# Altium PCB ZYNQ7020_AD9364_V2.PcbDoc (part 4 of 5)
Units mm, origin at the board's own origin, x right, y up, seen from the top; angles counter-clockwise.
Board outline 88.95 x 91.52 mm, 4 copper layers (Top Layer, Layer 1, Layer 2, Bottom Layer), stack 0.603 mm thick; 285 components, 278 nets, 1497 pads, 1247 vias.
Unrouted connection lines stored in the file: 367.
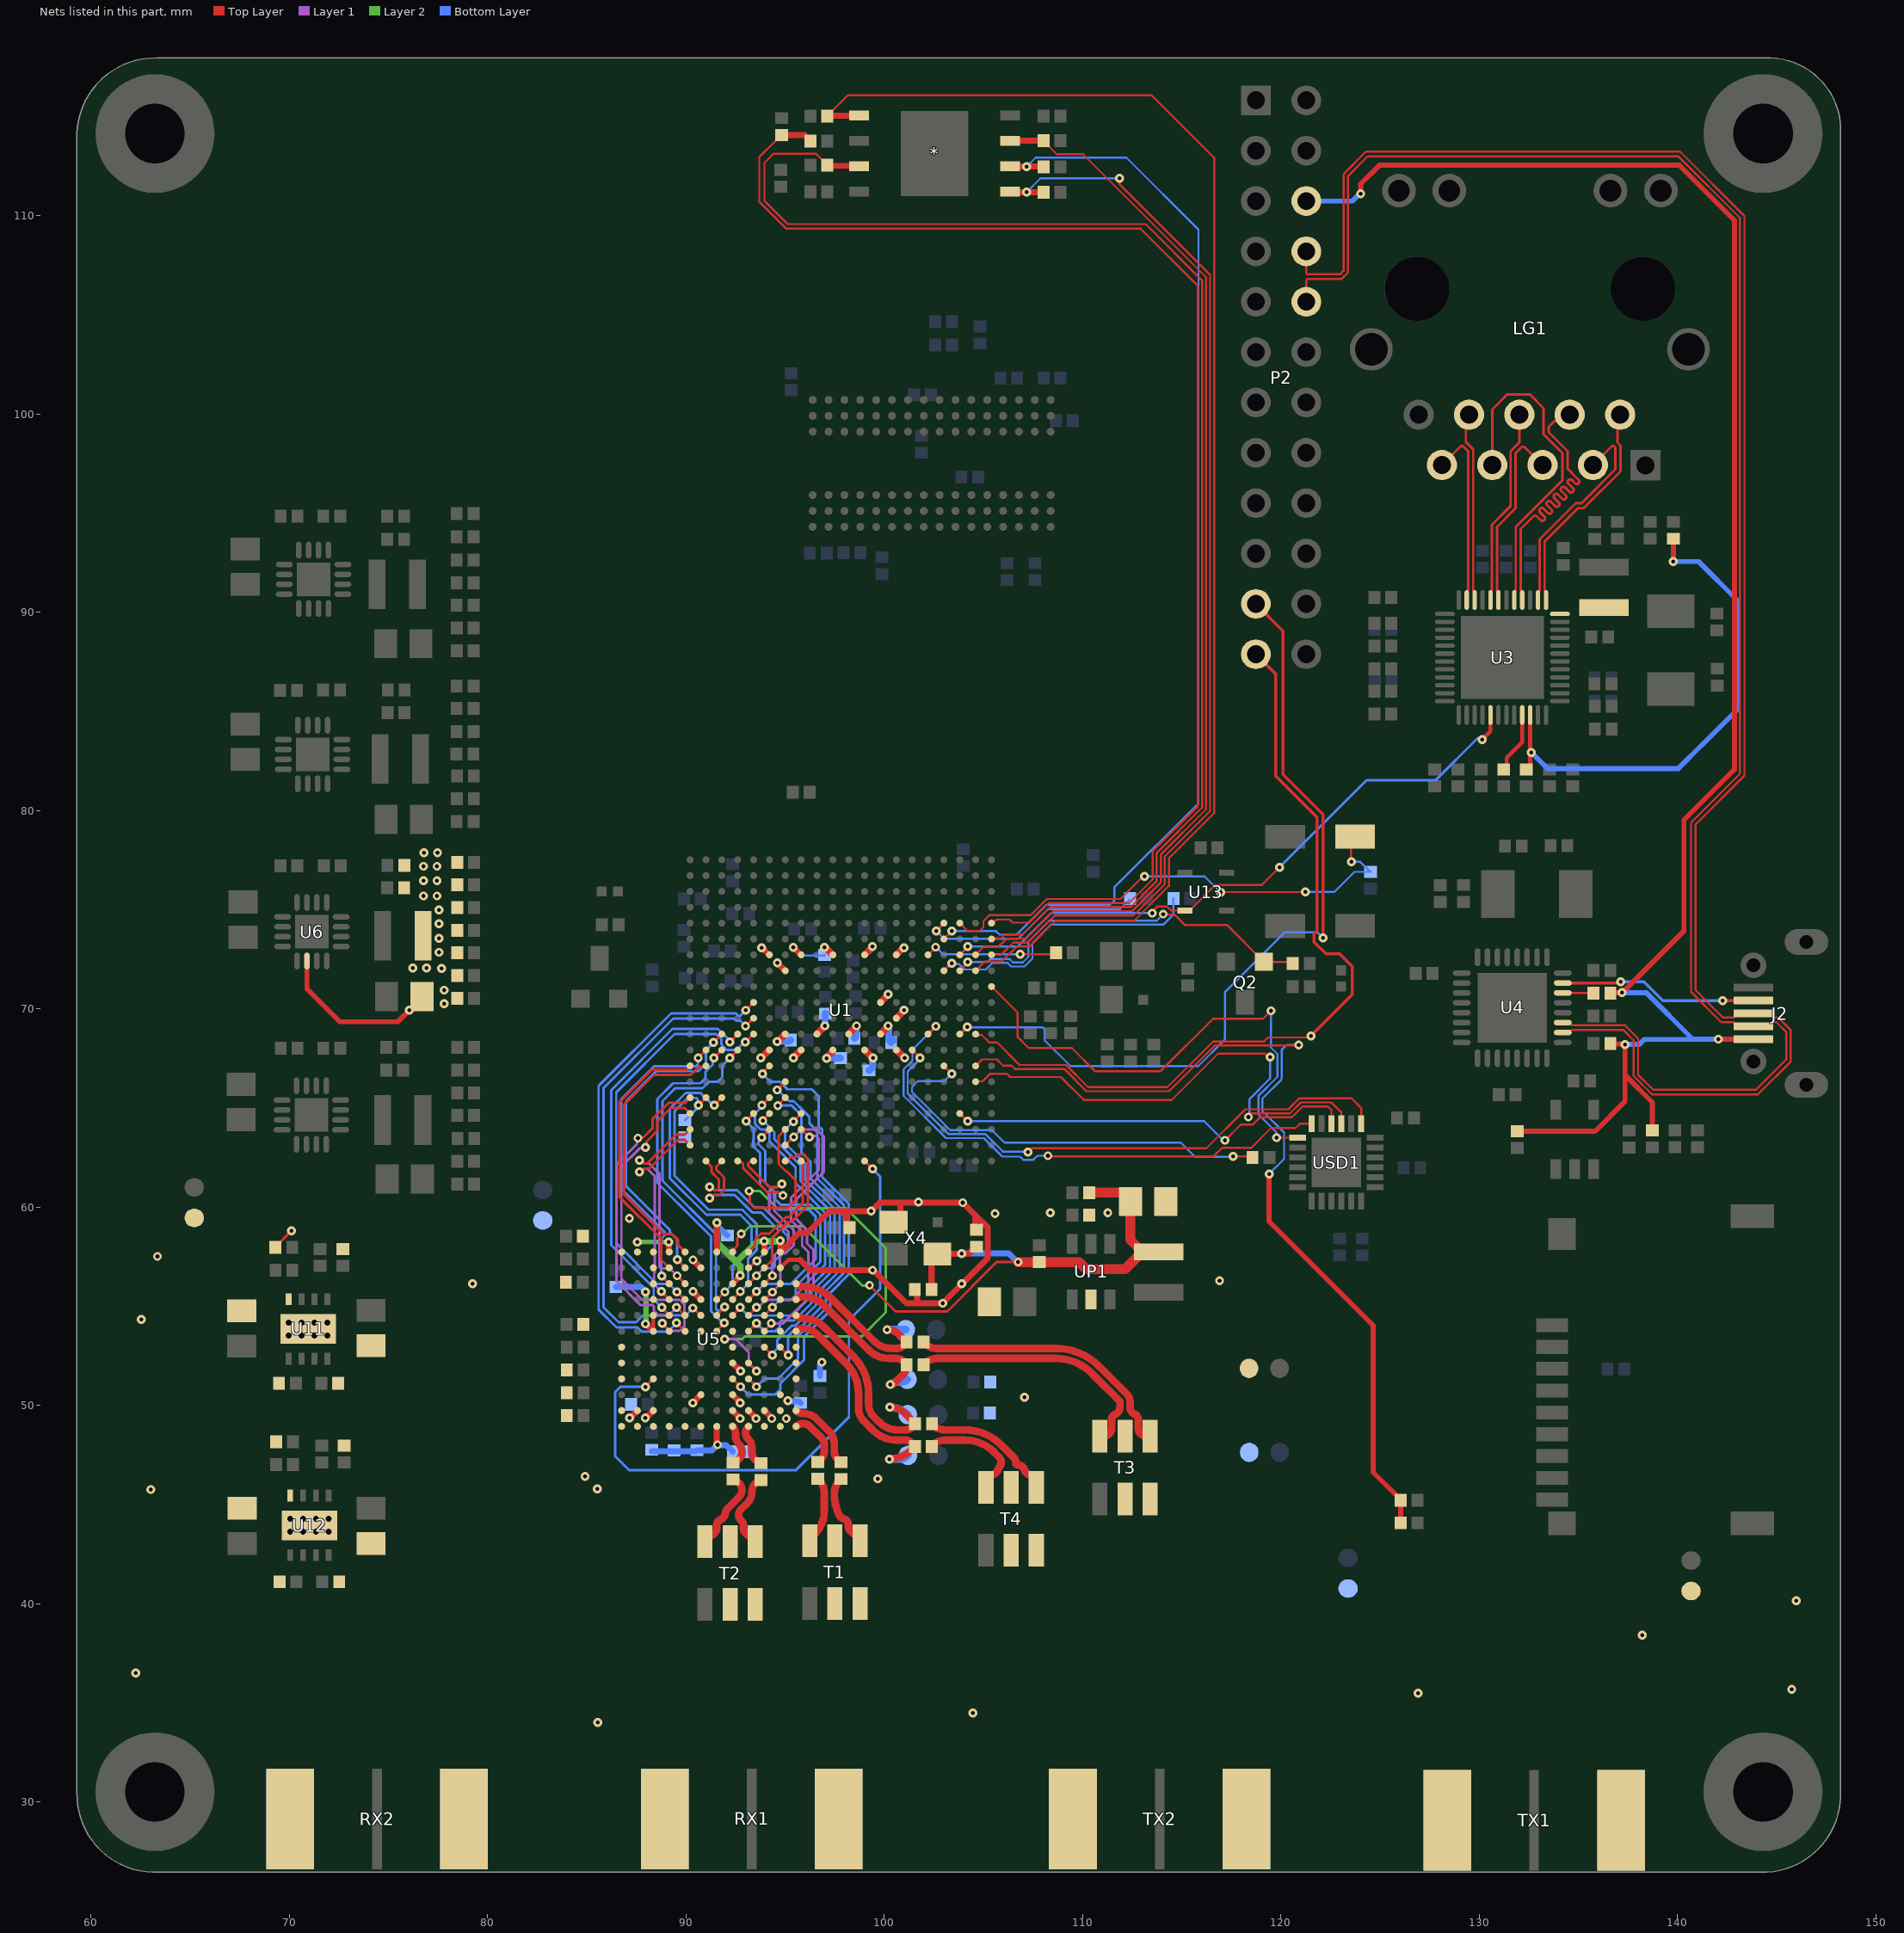
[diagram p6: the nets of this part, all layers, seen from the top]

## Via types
v1: diameter 0.45, hole 0.2, Top Layer to Bottom Layer, tented both sides, 995 vias
v2: diameter 0.406, hole 0.254, Top Layer to Bottom Layer, tented both sides, 118 vias
v3: diameter 1, hole 0.5, Top Layer to Bottom Layer, 116 vias
v4: diameter 0.5, hole 0.3, Top Layer to Bottom Layer, tented both sides, 16 vias
v5: diameter 0.406, hole 0.254, Top Layer to Bottom Layer, 2 vias

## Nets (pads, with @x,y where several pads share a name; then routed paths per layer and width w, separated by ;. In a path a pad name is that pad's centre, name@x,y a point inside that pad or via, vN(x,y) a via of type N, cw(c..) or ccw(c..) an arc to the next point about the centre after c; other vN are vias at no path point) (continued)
PHY_AD1/LED1: R32.1 R40.2 U3.34 | length 25.5
  Top Layer w0.203: R40.2@132.386,82.068 132.576,82.258 U3.34@132.576,84.818
  Top Layer w0.254: v1@139.802,92.583 R32.1@139.802,93.707
  Bottom Layer w0.254: v1(132.632,82.934) 133.447,82.118 140.05,82.118 141.26,83.327 141.265,83.327 143.053,85.115 143.053,90.576 141.069,92.561 v1(139.794,92.561)
PHY_MDI0_N: LG1.P3 U3.2 | length 11
  Top Layer w0.127: U3.2@132.976,90.618 132.976,91.033 133.049,91.106 133.049,93.674 134.877,95.503 135.168,95.503 136.878,97.213 136.878,98.306 136.804,98.381 136.699,98.381 LG1.P3@135.743,97.425
PHY_MDI0_P: LG1.P2 U3.1 | length 11.2
  Top Layer w0.127: U3.1@133.376,90.618 133.376,91.033 133.303,91.106 133.303,93.569 134.982,95.249 135.273,95.249 137.132,97.108 137.132,98.412 136.984,98.56 136.984,99.837 LG1.P2@137.112,99.965
PHY_MDI1_N: LG1.P7 U3.5 | length 17.1
  Top Layer w0.127: LG1.P7@130.663,97.425 130.663,100.233 131.42,100.99 132.563,100.99 133.254,100.299 133.254,98.975 133.328,98.901 134.212,98.017 134.212,96.671 131.849,94.308 131.849,91.106 131.776,91.033 U3.5@131.776,90.618
PHY_MDI1_P: LG1.P4 U3.4 | length 17.1
  Top Layer w0.127: U3.4@132.176,90.618 132.176,91.033 132.103,91.106 132.103,94.202 132.552,94.651 132.776,94.876 132.884,94.876 133.146,94.613 133.254,94.613 133.326,94.685 133.326,94.793 133.046,95.073 133.046,95.181 133.117,95.253 133.225,95.253 133.506,94.973 133.613,94.973 133.685,95.044 133.685,95.152 133.405,95.433 133.405,95.54 133.477,95.612 133.584,95.612 133.865,95.332 133.973,95.332 134.044,95.404 134.044,95.511 133.764,95.792 133.764,95.9 133.836,95.971 133.944,95.971 134.224,95.691 134.332,95.691 134.404,95.763 134.404,95.871 134.123,96.151 134.123,96.259 134.195,96.331 134.303,96.331 134.583,96.05 134.691,96.05 134.763,96.122 134.763,96.23 134.473,96.52 134.473,96.628 134.545,96.7 134.652,96.7 134.876,96.475 134.984,96.475 135.056,96.547 135.056,96.655 134.466,97.245 134.466,97.361 134.466,98.122 133.508,99.08 133.508,99.349 133.801,99.642 133.871,99.642 134.194,99.965 LG1.P4@134.572,99.965
PHY_MDI2_N: LG1.P6 U3.8 | length 9.9
  Top Layer w0.127: U3.8@130.576,90.618 130.576,91.033 130.649,91.106 130.649,94.415 131.59,95.356 131.59,98.13 132.032,98.572 LG1.P6@132.032,99.965
PHY_MDI2_P: LG1.P5 U3.7 | length 9.7
  Top Layer w0.127: U3.7@130.976,90.618 130.976,91.033 130.903,91.106 130.903,94.31 131.844,95.251 131.844,98.025 132.17,98.352 132.276,98.352 LG1.P5@133.203,97.425
PHY_MDI3_N: LG1.P9 U3.11 | length 9.4
  Top Layer w0.127: LG1.P9@128.123,97.425 129.079,98.381 129.184,98.381 129.449,98.116 129.449,91.106 129.376,91.033 U3.11@129.376,90.618
PHY_MDI3_P: LG1.P8 U3.10 | length 9.6
  Top Layer w0.127: LG1.P8@129.492,99.965 129.332,99.805 129.332,98.592 129.703,98.221 129.703,91.106 129.776,91.033 U3.10@129.776,90.618
PMEB: R35.2 U3.33 | length 3.1
  Top Layer w0.203: R35.2@131.243,82.068 131.395,82.221 131.395,82.659 132.176,83.44 U3.33@132.176,84.818
PS_CLK_500: R37.1 U1.E7 | length 6.8
  Top Layer w0.102: U1.E7@102.21,72.72 102.21,72.723 v1(102.595,73.11) v1(102.595,73.11) ; v1(106.858,72.746) 108.585,72.746 R37.1@108.661,72.822
  Bottom Layer w0.102: v1(102.595,73.11) 102.611,73.11 102.976,72.746 v1(106.858,72.746)
PS_MIO7: R56.2 U1.D8 | length 14.4
  Top Layer w0.127: U1.D8@103.01,71.92 v1@103.403,72.314
  Bottom Layer w0.102: v1(103.403,72.288) 103.442,72.25 103.781,72.25 104.047,71.984 105.123,71.984 105.454,72.315 106.222,72.315 106.401,72.136 107.069,72.136 107.471,72.538 107.471,73.318 108.398,74.244 114.072,74.244 114.586,74.759 R56.2@114.586,75.565
PS_MIO8: R47.2 U1.D5 | length 11.2
  Top Layer w0.127: v1(102.633,73.923) 102.633,73.933 103.01,74.31 U1.D5@103.01,74.32
  Bottom Layer w0.102: v1(102.633,73.923) 103.023,73.533 106.756,73.533 108.255,75.032 111.893,75.032 R47.2@112.349,75.487
PS_PRO_B: U1.C7 U3.29 U13.2 | length 32.6
  Top Layer w0.102: U1.C7@103.81,72.72 104.203,73.114 v1(104.203,73.136) ; v1(113.516,74.825) 113.516,74.908 113.763,75.155 114.28,75.155 114.479,74.955 U13.2@115.174,74.955 115.402,74.955 116.698,76.251 119.05,76.251 v1(119.939,77.14)
  Top Layer w0.203: v1(130.153,83.576) 130.576,83.999 U3.29@130.576,84.818
  Bottom Layer w0.102: v1(104.203,73.136) 106.715,73.136 108.407,74.828 113.512,74.828 v1(113.516,74.825)
  Bottom Layer w0.127: v1(119.939,77.14) 124.333,81.534 127.813,81.534 129.936,83.657 130.079,83.657 130.079,83.651 v1(130.153,83.576)
QSPI_CS: *.1 R59.1 U1.A7 | length 55.3
  Top Layer w0.102: U1.A7@105.41,72.72 105.893,72.72 106.513,73.341 107.242,73.341 108.602,74.701 112.571,74.701 114.148,76.278 114.148,77.648 ; v1(111.862,111.887) 111.862,111.598 116.434,107.026 116.434,79.979 114.148,77.693
  Top Layer w0.3: *.1@106.34,111.212 106.358,111.194 v1(107.186,111.194) 108.015,111.194 R59.1@108.033,111.176
  Bottom Layer w0.102: v1(107.186,111.194) 107.88,111.887 v1(111.862,111.887)
QSPI_D0: *.5 R49.2 U1.B8 | length 72.1
  Top Layer w0.102: R49.2@97.123,115.037 97.123,115.062 97.372,115.311 97.397,115.311 98.164,116.078 113.487,116.078 116.637,112.928 116.637,79.869 114.358,77.59 114.358,76.201 112.605,74.447 108.636,74.447 107.326,73.138 106.669,73.138 105.91,72.379 105.068,72.379 U1.B8@104.61,71.92
  Top Layer w0.3: R49.2@97.123,115.037 97.13,115.044 98.732,115.044 *.5@98.74,115.052
QSPI_D1: *.2 R51.2 U1.D6 | length 57.2
  Top Layer w0.102: U1.D6@103.01,73.52 103.403,73.914 v1(103.403,73.918)
  Top Layer w0.3: *.2@106.34,112.492 106.35,112.481 v1(107.186,112.481) 108.023,112.481 R51.2@108.033,112.471
  Bottom Layer w0.102: v1(103.403,73.918) 105.635,73.918 105.813,73.74 106.676,73.74 108.171,75.235 111.371,75.235 111.603,75.467 111.603,76.119 115.849,80.365 115.849,109.296 112.217,112.928 107.633,112.928 v1(107.186,112.481)
QSPI_D2: *.3 R52.2 U1.B7 | length 55.1
  Top Layer w0.102: U1.B7@104.61,72.72 105.016,73.127 105.766,73.127 106.183,73.544 107.158,73.544 108.544,74.93 112.513,74.93 113.944,76.362 113.944,77.777 116.23,80.063 116.23,106.898 110.023,113.106 108.701,113.106 108.04,113.767 R52.2@108.04,113.792
  Top Layer w0.3: *.3@106.34,113.772 106.35,113.782 108.03,113.782 R52.2@108.04,113.792
QSPI_D3: *.7 R50.2 U1.A6 | length 71.7
  Top Layer w0.102: R50.2@97.123,112.547 97.123,112.572 96.564,113.132 94.412,113.132 93.955,112.674 93.955,110.748 95.125,109.578 113.188,109.578 116.027,106.739 116.027,80.148 113.741,77.862 113.741,76.446 112.428,75.133 108.371,75.133 106.985,73.747 106.099,73.747 105.901,73.55 105.439,73.55 U1.A6@105.41,73.52
  Top Layer w0.3: R50.2@97.123,112.547 97.151,112.519 98.712,112.519 *.7@98.74,112.492
QSPI_SCK: R53.2 R58.2 U1.A5 | length 69.4
  Top Layer w0.102: R53.2@94.818,114.078 94.793,114.078 94.544,113.829 94.544,113.804 93.701,112.961 93.701,110.715 95.068,109.347 112.928,109.347 115.824,106.451 115.824,80.232 113.538,77.946 113.538,76.53 112.344,75.336 108.287,75.336 107.296,74.346 106.473,74.346 106.324,74.495 105.651,74.495 105.477,74.32 U1.A5@105.41,74.32
  Top Layer w0.3: R53.2@94.818,114.078 95.986,114.078 96.273,113.792 R58.2@96.273,113.767
REG_OUT: L6.1 U3.48 | length 0.8
  Top Layer w0.203: L6.1@135.528,90.246 L6.1@136.296,90.246
RFGND: C17.1 C18.1 C20.1 C21.1 C22.1 C23.1 C25.1 C26.1 C27.1 C28.1 C58.2 C59.1 C60.2 C63.1 C142.2 C143.1 C144.1 C145.1 C146.1 C150.1 C151.1 C166.2 C170.2 C172.2 C174.2 C175.2 C177.2 CP1.1 CP3.1 R24.2 R25.2 R75.2 RP1.2 RX1.2 RX1.3 RX1.4 RX1.5 RX2.2 RX2.3 RX2.4 RX2.5 RX5.1 RX6.1 RX7.1 RX8.1 RX10.1 RX13.1 RX14.1 RX15.1 RX22.1 T1.1 T1.2 T1.5 T2.1 T2.2 T2.5 T3.1 T3.2 T3.5 T4.1 T4.2 T4.5 TX1.2 TX1.3 TX1.4 TX1.5 TX2.2 TX2.3 TX2.4 TX2.5 U5.A1 U5.A2 U5.A4 U5.A5 U5.A6 U5.A12 U5.B1 U5.B2 U5.B12 U5.C1 U5.C2 U5.C7 U5.C8 U5.C9 U5.C10 U5.C11 U5.C12 U5.D1 U5.D12 U5.E1 U5.F1 U5.F3 U5.F7 U5.F9 U5.F11 U5.G1 U5.G12 U5.H2 U5.H3 U5.H5 U5.H6 U5.H7 U5.H10 U5.J2 U5.K1 U5.K2 U5.K12 U5.L1 U5.L2 U5.L3 U5.L7 U5.L8 U5.L9 U5.L10 U5.L11 U5.L12 U5.M4 U5.M5 U5.M6 U11.0 U11.4 U12.0 U12.4 UP1.2 X4.2 | length 59.5
  Top Layer w0.127: R24.2@69.296,57.967 69.296,57.992 v1@70.105,58.801
  Top Layer w0.2: U5.C7@88.354,53.734 88.354,53.747 U5.C8@88.354,54.534
  Top Layer w0.203: U5.L11@94.754,56.934 95.154,57.334 95.765,57.334
  Top Layer w0.3: U5.G1@91.554,48.934 91.554,48.044 v1(91.592,48.006) ; U5.H10@92.354,56.134 v1@92.705,56.485
  Top Layer w0.305: v1@87.181,49.361 U5.B2@87.554,49.734 ; v1(87.951,54.104) 87.971,54.104 88.331,53.744 88.351,53.744 U5.C7@88.354,53.747 ; v1@87.981,49.361 U5.C2@88.354,49.734 ; v1(89.138,58.24) 89.146,58.232 89.146,57.742 U5.D12@89.148,57.741 ; v1(90.354,55.734) U5.F9@90.754,55.334 ; v1(90.357,57.334) v1(90.357,57.334) 90.754,56.935 U5.F11@90.754,56.934 ; v1@90.381,50.161 U5.F3@90.754,50.534 ; U5.G12@91.554,57.734 91.567,57.747 v1(91.567,59.207) ; U5.H2@92.354,49.734 v1@92.727,49.361 ; U5.H3@92.354,50.534 v1@92.727,50.161 ; U5.H5@92.354,52.134 v1(92.754,51.734) ; U5.J2@93.154,49.734 v1@93.527,49.361 ; v1(93.949,58.273) 93.952,58.27 93.952,57.737 U5.K12@93.954,57.734 ; U5.K2@93.954,49.734 v1@94.328,49.361 ; U5.L12@94.754,57.734 95.694,58.674 96.114,58.674 97.231,59.792 97.866,59.792 ; U5.L12@94.756,57.758 94.756,58.3 v1(94.758,58.302) ; v1@95.034,49.357 v1(95.062,49.329) ; 95.765,57.334 96.285,56.814 v1(99.406,56.814) 99.447,56.814 101.117,55.143 101.752,55.143 ; C150.1@98.247,58.953 98.1,59.101 98.1,59.558 97.866,59.792 ; X4.2@100.482,59.233 100.813,59.563 100.813,60.223 ; C143.1@101.537,55.829 101.651,55.716 101.651,55.245 101.752,55.143 ; C144.1@104.648,58.852 104.595,58.905 104.595,59.591 ; 97.866,59.792 v1(99.339,59.792) 99.771,60.223 100.813,60.223 ; 100.813,60.223 v1(103.962,60.223) 104.595,59.591 ; 101.752,55.143 v1(102.946,55.143) 105.227,57.424 105.227,58.041 105.227,58.958 104.595,59.591
  Layer 2 w0.127: v1@89.129,58.232 v1(89.138,58.24) ; 92.519,57.239 92.547,57.239
  Layer 2 w0.25: v1(87.546,58.232) v1@89.129,58.232
  Layer 2 w0.3: v1@87.981,54.104 v1@87.981,55.753 ; 92.547,57.239 93.581,58.273 v1(93.949,58.273)
  Layer 2 w0.35: v1(91.567,59.207) 91.567,58.191 92.519,57.239 92.735,57.023 v1(92.735,56.54) ; v1(93.949,58.273) v1@94.758,58.273
  Bottom Layer w0.3: C170.2@86.462,55.963 87.73,55.963 87.94,55.753 v1@87.981,55.753 ; C172.2@88.265,47.679 90.497,47.679 C174.2@90.551,47.733 91.32,47.733 v1(91.592,48.006) 91.621,47.977 92.034,47.977 92.186,47.825 92.211,47.825 92.361,47.675 RX5.1@92.361,47.65 ; C166.2@96.749,51.479 96.749,52.07 v1(96.85,52.172)
  Bottom Layer w0.305: v1(91.567,59.207) 91.595,59.18 91.595,59.046 92.075,58.566 RX22.1@92.1,58.566 ; v1(95.148,50.236) 95.175,50.208 95.696,50.208 R75.2@95.783,50.121
  other v1: 85.554,33.999 104.477,34.482 126.93,35.472 145.767,35.665 62.252,36.504 138.223,38.409 145.99,40.148 63.014,45.749 85.528,45.785 99.676,46.293 84.912,46.406 92.727,49.329 93.527,49.329 94.328,49.329 87.149,49.361 87.949,49.361 90.348,50.114 92.727,50.129 107.068,50.407 62.531,54.334 87.96,55.728 79.244,56.138 103.911,56.134 116.913,56.29 63.344,57.509 70.105,58.808 87.147,59.436 105.588,59.665 108.382,59.715 111.274,59.719 101.727,60.249
  other v4: 70.038,43.618 70.688,43.618 71.338,43.618 71.988,43.618 70.038,44.268 70.688,44.268 71.338,44.268 71.988,44.268 69.967,53.523 70.617,53.523 71.267,53.523 71.917,53.523 69.967,54.173 70.617,54.173 71.267,54.173 71.917,54.173
RX1A_N: C16.2 U5.M2 | length 3.8
  Top Layer w0.381: U5.M2@95.554,49.734 ccw(c95.907,50.087) 95.907,49.588 cw(c95.907,48.599) 96.606,49.298 97.211,48.694 cw(c96.548,48.032) 97.485,48.032 97.485,47.65 ccw(c98.006,47.65) 97.638,47.281 97.773,47.146 ccw(c97.815,47.189) C16.2@97.815,47.129
RX1A_P: C30.2 U5.M1 | length 3
  Top Layer w0.381: U5.M1@95.554,48.934 95.557,48.937 cw(c95.903,48.59) 95.903,49.08 cw(c95.903,48.59) 96.25,48.937 96.85,48.336 cw(c96.544,48.03) 96.977,48.03 96.977,47.663 cw(c96.456,47.663) 96.825,47.295 96.69,47.16 cw(c96.647,47.203) C30.2@96.647,47.142
RX1AN_N: C16.1 T1.6 | length 3.2
  Top Layer w0.381: 97.485,45.526 ccw(c100.025,45.527) 97.706,44.491 ccw(c98.054,44.646) 97.961,44.276 ccw(c98.054,44.646) 97.962,44.276 cw(c97.892,43.993) 98.184,43.993 98.184,43.911 ccw(c98.565,43.911) 98.229,43.731 98.295,43.665 T1.6@98.455,43.505 ; 97.485,45.527 97.485,45.567 cw(c98.467,45.567) 97.773,46.261 cw(c97.815,46.218) C16.1@97.815,46.279
RX1AN_P: C30.1 T1.4 | length 3.5
  Top Layer w0.381: T1.4@96.241,43.167 96.241,43.179 cw(c96.617,43.124) 96.484,43.48 ccw(c95.294,44.671) 96.808,43.935 ccw(c96.466,44.102) 96.841,44.039 cw(c97.13,43.993) 96.88,44.144 ; C30.1@96.647,46.292 cw(c96.647,46.232) 96.69,46.275 cw(c95.996,45.581) 96.977,45.581 96.977,44.671 cw(c95.294,44.671) 96.922,44.244 cw(c96.554,44.341) 96.88,44.145
RX1B_N: C29.2 U5.J1 | length 2.2
  Top Layer w0.381: U5.J1@93.154,48.934 93.134,48.914 ccw(c93.438,48.61) 93.008,48.61 ccw(c93.438,48.61) 93.134,48.306 cw(c92.656,47.828) 93.332,47.828 93.332,47.575 ccw(c93.713,47.575) 93.444,47.306 93.516,47.234 ccw(c93.611,47.329) 93.611,47.194 cw(c93.611,47.059) 93.707,47.155 C29.2@93.777,47.085
RX1B_P: C31.2 U5.H1 | length 2.2
  Top Layer w0.381: U5.H1@92.354,48.934 cw(c92.002,48.582) 92.5,48.582 92.5,48.451 ccw(c93.053,48.451) 92.662,48.059 92.664,48.058 cw(c92.276,47.67) 92.824,47.67 92.824,47.601 cw(c92.443,47.601) 92.713,47.331 92.641,47.259 cw(c92.545,47.355) 92.545,47.22 ccw(c92.545,47.085) 92.45,47.18 C31.2@92.38,47.11
RX1BN_N: C29.1 T2.6 | length 3.9
  Top Layer w0.381: T2.6@93.497,43.129 ccw(c93.221,43.129) 93.417,43.324 93.402,43.339 ccw(c93.172,43.109) 93.172,43.434 cw(c93.281,43.799) 92.9,43.799 92.9,43.955 ccw(c92.608,43.955) 92.794,44.18 cw(c93.036,44.475) 92.767,44.744 93.097,45.075 ccw(c92.529,45.642) 93.332,45.641 cw(c93.959,45.642) 93.516,46.086 cw(c93.611,45.99) 93.611,46.125 ccw(c93.611,46.26) 93.707,46.165 C29.1@93.777,46.235
RX1BN_P: C31.1 T2.4 | length 4.1
  Top Layer w0.381: T2.4@90.957,43.129 cw(c91.331,43.053) 91.201,43.411 91.303,43.448 ccw(c91.173,43.806) 91.554,43.808 91.554,43.955 cw(c91.846,43.955) 91.742,44.228 ccw(c91.601,44.581) 91.978,44.53 cw(c92.476,44.461) 92.121,44.817 92.68,45.376 ccw(c92.333,45.724) 92.824,45.724 ccw(c92.333,45.724) 92.68,46.072 92.641,46.111 ccw(c92.545,46.016) 92.545,46.151 cw(c92.545,46.286) 92.45,46.19 C31.1@92.38,46.26
RX_D0_N: U1.P20 U5.K11 | length 7.9
  Top Layer w0.127: U5.K11@93.954,56.934 94.339,57.319 94.339,58.435 95.143,59.238 95.303,59.238 96.15,60.085 96.15,62.461 95.951,62.661 95.669,62.661 95.519,62.51 95.26,62.51 95.07,62.32 U1.P20@95.01,62.32
RX_D0_P: U1.N20 U5.J12 | length 6.1
  Top Layer w0.127: U5.J12@93.154,57.734 93.493,58.073 93.493,58.368 93.788,58.663 94.208,58.663 95.037,59.492 95.198,59.492 95.896,60.19 U1.N20@95.896,62.351
RX_D1_N: U1.W20 U5.K10 | length 10.2
  Top Layer w0.127: U1.W20@91.01,62.32 91.283,62.047 91.283,61.774 91.66,61.397 91.66,60.933 91.585,60.858 91.422,60.858 91.269,61.011 v1(91.186,61.011) ; U5.K10@93.954,56.134 v1(94.354,56.534)
  Bottom Layer w0.127: v1(91.186,61.011) 91.269,61.011 91.422,60.858 92.572,60.858 93.447,59.984 93.888,59.984 94.907,58.964 94.907,58.749 95.148,58.507 95.148,57.962 94.354,57.168 v1(94.354,56.534)
RX_D1_P: U1.V20 U5.J11 | length 9.5
  Top Layer w0.127: v1(91.186,60.452) 91.269,60.452 91.422,60.604 91.69,60.604 91.914,60.828 91.914,61.502 91.537,61.879 91.537,62.047 U1.V20@91.81,62.32 ; U5.J11@93.154,56.934 93.178,56.934 93.553,57.309 v1(93.574,57.288)
  Bottom Layer w0.127: v1(91.186,60.452) 91.269,60.452 91.422,60.604 92.467,60.604 93.341,59.73 93.783,59.73 94.653,58.859 94.653,58.749 94.339,58.435 94.339,58.072 93.675,57.408 93.574,57.306 v1(93.574,57.288)
RX_D2_N: U1.U20 U5.K9 | length 10.2
  Top Layer w0.127: U1.U20@92.61,62.32 92.653,62.278 92.787,62.278 92.883,62.182 92.883,61.971 93.682,61.172 93.684,61.172 94.108,60.749 94.655,60.749 94.815,60.588 v1(94.891,60.588) ; U5.K9@93.954,55.321 93.966,55.321 94.354,55.709 v1(94.354,55.711)
  Layer 1 w0.127: v1(94.354,55.711) 94.761,56.118 94.761,57.062 94.733,57.09 94.733,57.489 94.902,57.658 95.025,57.658 95.428,58.061 95.428,58.843 94.458,59.812 94.458,60.484 94.425,60.517 94.425,60.674 94.5,60.749 94.655,60.749 94.815,60.588 v1(94.891,60.588)
RX_D2_P: U1.T20 U5.J10 | length 9.7
  Top Layer w0.127: U5.J10@93.154,56.134 93.554,56.534 v1(93.557,56.534) ; U1.T20@93.41,62.32 93.367,62.278 93.233,62.278 93.137,62.182 93.137,62.076 93.787,61.426 93.79,61.426 94.213,61.003 94.608,61.003 94.768,61.163 v1(94.844,61.163)
  Layer 1 w0.127: v1(93.557,56.534) 93.833,56.811 93.837,56.811 93.95,56.924 94.421,56.924 94.48,56.984 94.479,56.985 94.479,57.595 94.796,57.912 94.92,57.912 95.174,58.166 95.174,58.738 94.204,59.707 94.204,60.357 94.171,60.39 94.171,60.779 94.394,61.003 94.608,61.003 94.768,61.163 v1(94.844,61.163)
RX_D3_N: U1.R18 U5.K8 | length 13.3
  Top Layer w0.127: v1(93.817,63.516) U1.R18@94.223,63.922 ; U5.K8@93.954,54.534 93.957,54.534 v1(94.354,54.931)
  Bottom Layer w0.127: v1(93.817,63.516) 93.817,63.448 93.65,63.28 93.65,63.175 94.004,62.821 94.004,61.219 94.007,61.216 94.097,61.126 94.426,60.797 94.501,60.722 94.501,60.392 94.771,60.122 96.283,60.122 96.785,59.62 96.785,57.254 95.538,56.007 95.538,55.902 95.544,55.896 95.544,55.573 95.293,55.321 94.744,55.321 v1(94.354,54.931)
RX_D3_P: U1.T17 U5.J9 | length 14.1
  Top Layer w0.127: v1(93.03,64.329) 93.03,64.335 93.423,64.728 U1.T17@93.423,64.729 ; U5.J9@93.154,55.334 93.554,55.734 v1(93.557,55.734)
  Bottom Layer w0.127: v1(93.03,64.329) 93.418,63.941 93.418,63.407 93.396,63.386 93.396,63.07 93.75,62.716 93.75,61.114 94.007,60.857 94.247,60.617 94.247,60.287 94.666,59.868 96.201,59.868 96.531,59.538 96.531,57.359 95.296,56.124 93.947,56.124 v1(93.557,55.734)
RX_D4_N: U1.P19 U5.K7 | length 14.6
  Top Layer w0.127: U5.K7@93.954,53.734 93.954,53.76 94.303,54.108 v1(94.303,54.134) ; U1.P19@95.01,63.127 95.411,63.528 95.428,63.528 v1(95.431,63.532)
  Layer 1 w0.127: v1(94.303,54.134) 94.906,54.134 96.234,55.462 96.234,55.891 96.431,56.087 96.431,57.842 96.112,58.161 96.112,58.854 95.555,59.411 95.555,60.372 96.952,61.769 96.952,63.554 96.588,63.918 95.818,63.918 v1(95.431,63.532)
RX_D4_P: U1.N18 U5.J8 | length 13.1
  Top Layer w0.127: U5.J8@93.154,54.534 U5.J8@93.154,54.534 v1(93.557,54.934) v1(93.557,54.934) ; U1.N18@95.816,63.92 v1@96.209,63.528
  Layer 1 w0.127: v1(93.557,54.934) 93.632,54.934 94.019,55.321 95.306,55.321 96.177,56.193 96.177,57.737 95.858,58.056 95.858,58.777 95.301,59.334 95.301,60.477 96.698,61.874 96.698,63.449 96.571,63.576 96.27,63.576 v1(96.222,63.528)
  Bottom Layer w0.127: v1(96.222,63.528) v1@96.222,63.581
RX_D5_N: U1.R17 U5.J7 | length 15.7
  Top Layer w0.127: U5.J7@93.154,53.734 v1(93.554,54.134) ; v1(93.874,64.362) 93.874,64.373 U1.R17@94.223,64.723
  Bottom Layer w0.127: v1(93.554,54.134) 93.944,53.744 94.516,53.744 94.744,53.973 94.744,54.2 94.819,54.274 95.451,54.274 96.32,55.143 96.32,56.036 97.267,56.983 97.267,59.82 95.783,61.304 95.783,62.103 95.098,62.789 94.461,63.425 94.461,63.778 93.878,64.362 v1(93.874,64.362)
RX_D5_P: U1.R16 U5.H8 | length 16.9
  Top Layer w0.127: U5.H8@92.354,54.534 92.726,54.906 v1(92.726,54.934) ; v1@93.83,65.136 U1.R16@94.223,65.529
  Bottom Layer w0.127: v1(92.726,54.934) 93.132,54.528 95.346,54.528 96.066,55.248 96.066,56.141 97.013,57.088 97.013,59.715 95.529,61.199 95.529,61.998 94.207,63.32 94.207,63.568 94.22,63.581 94.22,63.678 93.992,63.906 93.777,63.906 93.484,64.2 93.484,64.714 93.83,65.06 v1(93.83,65.132)
RX_FRAME_N: U1.V13 U5.G7 | length 17.9
  Top Layer w0.127: v1@91.417,67.523 U1.V13@91.81,67.916 ; U5.G7@91.554,53.734 91.554,53.76 91.929,54.134 v1@91.954,54.134
  Bottom Layer w0.127: v1(91.417,67.518) 91.355,67.456 91.355,67.191 90.977,66.813 90.977,66.491 90.729,66.243 89.35,66.243 88.56,65.453 88.56,61.224 90.575,59.209 90.754,59.03 91.262,58.522 91.262,54.743 91.598,54.407 91.606,54.407 91.848,54.166 v1(91.935,54.166)
RX_FRAME_P: U1.U13 U5.G8 | length 18
  Top Layer w0.127: U5.G8@91.554,54.534 91.554,54.548 91.946,54.94 v1(91.946,54.953) ; v1(92.21,67.518) v1(92.21,67.518) 92.607,67.916 U1.U13@92.61,67.916
  Bottom Layer w0.127: v1(91.946,54.953) 91.892,54.953 91.652,54.713 91.516,54.848 91.516,58.627 88.814,61.329 88.814,65.348 89.455,65.989 90.834,65.989 91.156,66.311 91.578,66.311 91.827,66.56 91.827,67.134 v1(92.21,67.518)
SD_CD: R70.2 R71.1 U1.B14 | length 48
  Top Layer w0.102: U1.B14@104.61,67.12 104.937,67.448 105.677,67.448 105.993,67.132 106.425,67.132 106.594,66.964 109.077,66.964 110.2,65.841 114.365,65.841 116.672,68.148 120.853,68.148 v1@120.929,68.224 ; R71.1@126.042,44.069 126.045,44.072 126.048,44.076 R70.2@126.048,45.212
  Top Layer w0.25: v1(119.411,61.67) 119.411,59.278 124.663,54.026 124.663,46.622 126.048,45.237 R70.2@126.048,45.212 126.045,45.209 R71.1@126.045,44.072
  Bottom Layer w0.102: v1(119.411,61.67) 120.167,62.426 120.167,63.754 119.073,64.849 119.073,65.467 120.037,66.431 120.037,66.544 120.04,66.548 120.04,67.92 120.294,68.174 v1(120.904,68.174)
SD_CLK: R72.2 U1.D14 | length 21.6
  Top Layer w0.102: v1(117.595,62.548) 118.535,62.548 R72.2@118.574,62.509
  Top Layer w0.127: U1.D14@103.01,67.12 v1@103.403,66.727
  Bottom Layer w0.102: v1(103.407,66.727) 103.03,66.35 101.696,66.35 101.397,66.05 101.397,65.811 103.327,63.881 105.435,63.881 106.07,63.246 114.96,63.246 115.672,62.535 v1@117.551,62.535
SD_CMD: U1.C17 USD1.4 | length 20.8
  Top Layer w0.102: v1@117.192,63.369 117.987,64.164 118.589,64.164 118.948,64.523 120.546,64.523 121.098,65.075 122.377,65.075 122.555,64.897 USD1.4@122.555,64.198
  Top Layer w0.127: U1.C17@103.81,64.72 v1@104.203,64.327
  Bottom Layer w0.102: v1@104.222,64.313 104.236,64.327 116.14,64.327 117.098,63.369 v1(117.191,63.369)
  Bottom Layer w0.127: v1(104.208,64.327) v1@104.222,64.313
SD_D0: U1.E12 USD1.6 | length 27.5
  Top Layer w0.102: v1@108.204,62.56 116.611,62.56 117.043,62.992 118.516,62.992 119.507,63.983 120.743,63.983 120.959,64.198 USD1.6@121.557,64.198
  Top Layer w0.127: U1.E12@102.21,68.72 v1@102.603,69.114
  Bottom Layer w0.102: v1(102.603,69.118) 101.422,67.937 101.422,67.387 100.98,66.944 100.98,65.612 103.117,63.475 105.021,63.475 105.952,62.544 106.849,62.544 107.007,62.386 107.522,62.386 107.721,62.585 v1(108.256,62.585)
SD_D1: U1.A9 USD1.7 | length 26
  Top Layer w0.102: U1.A9@105.41,71.12 106.731,69.799 106.731,68.57 107.28,68.021 109.457,68.021 110.621,66.857 113.944,66.857 116.582,69.494 119.101,69.494 v1(119.507,69.901) ; v1@119.992,63.497 USD1.7@120.856,63.497
  Bottom Layer w0.102: v1(119.507,69.901) 119.507,68.047 119.834,67.72 119.834,66.57 118.869,65.606 118.869,64.678 119.786,63.761 v1(119.786,63.5)
SD_D2: U1.F13 USD1.1 | length 28.8
  Top Layer w0.102: v1(107.239,62.763) 107.442,62.967 116.249,62.967 118.212,64.93 120.378,64.93 120.929,65.481 123.571,65.481 124.056,64.996 USD1.1@124.056,64.198
  Top Layer w0.127: U1.F13@101.41,67.92 v1@101.803,67.527
  Bottom Layer w0.102: v1(101.807,67.527) 101.807,67.467 101.183,66.842 101.183,65.738 103.243,63.678 105.105,63.678 105.994,62.789 v1@107.239,62.789
SD_D3: U1.B15 USD1.3 | length 25.8
  Top Layer w0.102: U1.B15@104.61,66.32 104.627,66.338 104.964,66.338 105.352,66.726 106.184,66.726 106.353,66.557 108.909,66.557 110.072,65.394 114.493,65.394 116.841,67.742 119.177,67.742 v1@119.384,67.534 ; v1@118.364,64.592 118.498,64.726 120.462,64.726 121.014,65.278 122.552,65.278 123.055,64.775 USD1.3@123.055,64.198
  Bottom Layer w0.102: v1(118.364,64.541) 118.428,64.605 118.428,65.451 119.456,66.48 v1(119.456,67.564)
SPI_CLK: U1.P18 U5.J5 | length 30.3
  Top Layer w0.127: U5.J5@93.154,52.134 v1(93.554,51.734) ; v1@93.218,60.706 93.218,60.173 93.432,59.959 95.149,59.959 95.513,60.323 95.513,61.369 95.1,61.782 95.067,61.782 94.67,62.18 94.67,63.576 U1.P18@95.01,63.916
  Layer 1 w0.127: v1(91.948,53.34) 92.5,53.34 93.167,52.672 93.167,52.121 v1(93.554,51.734)
  Layer 2 w0.127: v1(91.948,53.34) 92.837,53.34 92.964,53.467 98.857,53.467 100.076,54.686 100.076,57.937 98.069,59.944 94.59,59.944 93.726,60.808 v1(93.193,60.808)
SPI_DI: U1.P15 U5.J4 | length 19.9
  Top Layer w0.127: U5.J4@93.154,51.334 v1(93.554,50.934) ; v1(94.604,65.906) 94.604,65.91 U1.P15@95.01,66.316
  Bottom Layer w0.127: v1(93.554,50.934) 93.554,51.009 93.629,51.009 93.966,51.346 94.653,51.346 95.656,52.349 95.656,53.481 97.056,54.881 97.056,55.776 97.98,56.7 97.98,60.077 96.622,61.436 96.622,63.827 96.224,64.224 96.224,64.551 95.983,64.792 95.43,65.345 95.19,65.345 94.629,65.906 v1(94.604,65.906)
SPI_DO: U1.P16 U5.L6 | length 16.6
  Top Layer w0.127: v1(94.63,65.116) 94.63,65.129 95.023,65.522 U1.P16@95.023,65.529 ; U5.L6@94.754,52.934 v1(95.154,52.534)
  Bottom Layer w0.127: v1(94.63,65.116) 95.335,65.116 95.822,64.63 95.822,62.751 96.272,62.3 96.272,61.462 97.752,59.982 97.752,56.794 96.785,55.827 96.785,54.933 95.649,53.797 95.446,53.797 95.158,53.509 95.158,52.538 v1(95.154,52.534)
SPI_ENB: U1.N17 U5.K6 | length 15.5
  Top Layer w0.127: U5.K6@93.954,52.934 v1(94.354,52.534) ; v1@95.417,64.323 U1.N17@95.81,64.716
  Bottom Layer w0.127: v1(94.354,52.534) 94.354,52.6 94.615,52.861 94.615,53.289 95.352,54.026 95.526,54.026 96.556,55.056 96.556,55.949 97.496,56.888 97.496,59.915 96.012,61.399 96.012,62.205 94.996,63.221 94.996,63.898 v1(95.417,64.318)
TEST/ENABLE: RX5.2 U1.J20 U5.C4 | length 33.8
  Top Layer w0.127: v1(87.954,50.918) 87.954,50.935 U5.C4@88.354,51.334 ; U1.J20@99.01,62.32 v1@99.403,61.927
  Bottom Layer w0.127: v1(87.954,50.918) 87.936,50.936 86.699,50.936 86.436,50.673 86.436,47.422 87.122,46.736 94.101,46.736 ; RX5.2@93.211,47.65 93.211,47.625 94.101,46.736 ; v1(99.407,61.927) 99.797,61.538 99.797,55.873 98.222,54.298 98.222,49.403 95.555,46.736 94.101,46.736
TX1A_N: C48.1 L9.2 U5.M8 | length 12
  Top Layer w0.381: U5.M8@95.554,54.534 ccw(c95.907,54.886) 95.907,54.388 95.909,54.388 cw(c95.909,52.912) 96.953,53.956 98.432,52.476 cw(c96.549,50.593) 99.212,50.593 99.212,50.057 ccw(c100.117,50.057) 99.477,49.418 ; 99.477,49.418 99.742,49.153 ccw(c100.702,50.112) 100.702,48.755 101.057,48.755 ccw(c101.057,49.255) 101.41,48.902 101.538,49.03 ccw(c101.496,49.073) C48.1@101.556,49.073 101.028,49.601 ccw(c100.279,48.852) v1@100.279,49.911
  Bottom Layer w0.381: v1(100.279,49.9) 100.291,49.9 cw(c100.291,48.636) L9.2@101.186,49.53
TX1A_P: C40.1 L8.2 U5.M7 | length 11.9
  Top Layer w0.381: U5.M7@95.554,53.734 cw(c95.907,53.382) 95.907,53.88 cw(c95.907,52.906) 96.595,53.595 98.069,52.121 cw(c96.536,50.588) 98.704,50.588 98.704,49.847 ccw(c99.609,49.847) 98.969,49.208 ; 98.969,49.207 99.46,48.717 ccw(c100.593,49.85) 100.593,48.247 101.05,48.247 cw(c101.05,47.748) 101.403,48.101 101.532,47.972 cw(c101.489,47.93) C40.1@101.549,47.93 101.381,47.762 cw(c100.254,48.889) v1@100.254,47.295
  Bottom Layer w0.381: v1(100.254,47.284) 100.739,47.284 ccw(c100.739,47.927) L8.2@101.194,47.473
TX1AN_N: C48.2 T4.6 | length 6.8
  Top Layer w0.381: C48.2@102.406,49.073 ccw(c102.466,49.073) 102.424,49.03 ccw(c103.087,49.694) 103.087,48.755 104.079,48.755 cw(c104.079,46.187) 105.895,48.003 106.507,47.391 cw(c106.152,47.035) 106.655,47.035 ccw(c106.865,47.353) 106.818,46.975 cw(c106.782,46.685) 107.063,46.763 ccw(c107.43,46.866) 107.345,46.494 cw(c107.345,46.169) 107.575,46.399 cw(c107.345,46.169) 107.671,46.169 T4.6@107.671,45.859
TX1AN_P: C40.2 T4.4 | length 5.7
  Top Layer w0.381: C40.2@102.399,47.93 cw(c102.732,47.744) 102.495,48.043 cw(c103.08,47.309) 103.08,48.247 104.074,48.247 cw(c104.074,46.175) 105.539,47.641 105.782,47.398 cw(c105.513,47.128) 105.799,46.877 ccw(c106.02,46.685) 105.739,46.765 cw(c105.373,46.871) 105.491,46.508 105.391,46.476 ccw(c105.507,46.113) 105.131,46.169 T4.4@105.131,45.859
TX1B_N: C47.1 L7.2 U5.M10 | length 9
  Top Layer w0.381: U5.M10@95.554,56.134 ccw(c95.907,56.487) 95.907,55.988 95.909,55.988 cw(c95.909,53.981) 97.328,55.4 99.511,53.217 ccw(c100.348,54.054) 100.348,52.87 100.632,52.87 ccw(c100.632,53.369) 100.985,53.016 101.113,53.145 ccw(c101.071,53.188) C47.1@101.131,53.188 100.739,53.579 ccw(c100.152,52.993) v1@100.152,53.823
  Bottom Layer w0.381: v1(100.142,53.815) 100.146,53.819 101.08,53.819 L7.2@101.084,53.823
TX1B_P: C32.1 L5.2 U5.M9 | length 9.2
  Top Layer w0.381: U5.M9@95.554,55.334 cw(c95.907,54.982) 95.907,55.48 cw(c95.907,53.977) 96.97,55.04 99.227,52.783 ccw(c100.243,53.8) 100.243,52.362 100.632,52.362 cw(c100.632,51.863) 100.985,52.216 101.113,52.087 cw(c101.071,52.045) C32.1@101.131,52.045 cw(c100.367,52.045) 100.907,51.504 100.565,51.162 cw(c100.305,51.422) v1@100.305,51.054
  Bottom Layer w0.381: v1(100.305,51.043) ccw(c100.305,51.089) 100.336,51.057 cw(c100.629,50.764) 100.629,51.178 100.854,51.178 ccw(c100.854,51.622) L5.2@101.168,51.308
TX1BN_N: C47.2 T3.6 | length 13.9
  Top Layer w0.381: C47.2@101.981,53.188 ccw(c102.041,53.188) 101.999,53.145 ccw(c102.662,53.808) 102.662,52.87 108.67,52.87 cw(c108.67,49.825) 110.822,51.979 cw(c108.67,49.825) 110.823,51.978 112.247,50.554 cw(c111.891,50.198) 112.395,50.198 112.395,49.899 ccw(c112.776,49.899) 112.632,49.546 cw(c112.522,49.276) 112.814,49.276 112.814,48.831 ccw(c113.195,48.831) 113.195,48.45 T3.6@113.411,48.45
TX1BN_P: C32.2 T3.4 | length 13.1
  Top Layer w0.381: C32.2@101.981,52.045 cw(c102.041,52.045) 101.999,52.087 cw(c102.662,51.424) 102.662,52.362 108.669,52.362 cw(c108.669,49.822) 110.465,51.618 111.887,50.196 111.887,49.9 cw(c111.506,49.899) 111.65,49.546 ccw(c111.76,49.276) 111.468,49.276 111.468,48.831 cw(c111.087,48.831) 111.087,48.45 T3.4@110.871,48.45
TX_D0_N: U1.T10 U5.E7 | length 26.1
  Top Layer w0.127: v1(89.526,54.15) 89.942,53.734 U5.E7@89.954,53.734 ; v1@93.019,69.927 93.41,70.318 U1.T10@93.41,70.32
  Bottom Layer w0.127: v1(89.526,54.15) 89.089,53.714 87.783,53.714 87.561,53.936 86.493,53.936 85.594,54.835 85.594,66.108 89.252,69.767 92.515,69.767 92.632,69.65 92.738,69.65 93.011,69.923 v1(93.017,69.923)
TX_D0_P: U1.T11 U5.F8 | length 26.1
  Top Layer w0.127: v1(90.348,54.906) 90.365,54.906 90.737,54.534 U5.F8@90.754,54.534 ; v1(93.006,69.123) 93.009,69.123 93.407,69.52 U1.T11@93.41,69.52
  Bottom Layer w0.127: v1(90.348,54.906) 89.983,54.541 87.836,54.541 87.561,54.266 87.561,54.264 87.487,54.19 86.598,54.19 85.848,54.94 85.848,56.015 85.848,66.003 89.357,69.513 92.41,69.513 92.527,69.396 92.738,69.396 93.006,69.128 v1(93.006,69.123)
TX_D1_N: U1.Y17 U5.D7 | length 17.6
  Top Layer w0.127: v1(87.96,63.017) 88.007,63.064 88.007,63.304 88.564,63.861 88.564,64.332 89.225,64.993 89.937,64.993 U1.Y17@90.21,64.72 ; v1(88.806,54.131) 88.806,54.107 89.154,53.758 U5.D7@89.154,53.734
  Layer 1 w0.127: v1(87.96,63.017) 87.913,62.97 87.674,62.97 86.743,62.039 86.743,56.375 87.797,55.321 89.687,55.321 89.916,55.093 89.916,53.989 89.687,53.76 89.176,53.76 v1(88.806,54.131)
TX_D1_P: U1.Y16 U5.E8 | length 16.1
  Top Layer w0.127: v1(87.579,63.475) 87.626,63.522 87.866,63.522 88.31,63.966 88.31,64.437 89.12,65.247 89.937,65.247 U1.Y16@90.21,65.52 ; v1(89.526,54.931) 89.542,54.931 89.939,54.534 U5.E8@89.954,54.534
  Layer 1 w0.127: v1(87.579,63.475) 87.532,63.428 87.532,63.188 86.489,62.144 86.489,56.27 87.691,55.067 88.313,55.067 88.387,54.993 88.387,54.765 88.616,54.537 89.131,54.537 v1(89.526,54.931)
TX_D2_N: U1.U12 U5.D8 | length 20.7
  Top Layer w0.127: v1(88.778,54.931) 89.154,54.554 U5.D8@89.154,54.534 ; v1@92.217,68.323 U1.U12@92.61,68.716
  Bottom Layer w0.127: v1(88.778,54.931) 88.371,55.338 88.371,55.931 86.228,58.074 86.228,65.896 89.319,68.986 91.62,68.986 92.217,68.39 v1(92.217,68.318)
TX_D2_P: U1.T12 U5.E9 | length 21.2
  Top Layer w0.127: v1@89.554,55.734 U5.E9@89.954,55.334 ; v1(92.997,68.318) 93.002,68.318 93.4,68.716 U1.T12@93.41,68.716
  Bottom Layer w0.127: v1@89.554,55.734 89.529,55.734 89.139,56.124 88.537,56.124 86.482,58.179 86.482,65.791 89.424,68.732 91.515,68.732 91.785,68.463 91.785,68.198 92.055,67.928 92.542,67.928 92.932,68.318 v1(92.997,68.318)
  other v1: 89.548,55.715
TX_D3_N: U1.Y19 U5.D9 | length 10.9
  Top Layer w0.127: v1(87.655,61.773) 87.726,61.773 87.891,61.938 88.147,61.938 89.603,63.393 89.937,63.393 U1.Y19@90.21,63.12 ; v1(88.761,55.734) 88.761,55.731 89.154,55.338 U5.D9@89.154,55.334
  Layer 1 w0.127: v1(87.655,61.773) 87.726,61.773 87.891,61.938 88.042,61.938 88.416,61.563 88.416,57.781 88.417,57.78 88.417,56.704 88.392,56.679 88.392,56.103 v1(88.761,55.734)
TX_D3_P: U1.Y18 U5.E10 | length 11
  Top Layer w0.127: v1(87.655,62.357) 87.726,62.357 87.891,62.192 88.042,62.192 89.497,63.647 89.937,63.647 U1.Y18@90.21,63.92 ; v1(89.554,56.534) U5.E10@89.954,56.134
  Layer 1 w0.127: v1(87.655,62.357) 87.726,62.357 87.891,62.192 88.147,62.192 88.67,61.669 88.67,57.855 88.671,57.854 88.671,56.982 88.746,56.907 89.181,56.907 v1(89.554,56.534)
TX_D4_N: U1.W13 U5.D10 | length 15.9
  Top Layer w0.127: v1(88.782,56.517) 88.782,56.512 89.154,56.14 U5.D10@89.154,56.134 ; v1@90.616,67.523 U1.W13@91.01,67.916
  Bottom Layer w0.127: v1(88.782,56.517) 88.748,56.552 88.748,58.402 88.923,58.578 88.923,58.744 86.728,60.94 86.728,65.439 88.392,67.103 90.517,67.103 90.608,67.194 90.608,67.509 v1(90.616,67.518)
TX_D4_P: U1.V12 U5.E11 | length 16.2
  Top Layer w0.127: v1@89.58,57.309 89.592,57.309 89.954,56.947 U5.E11@89.954,56.934 ; v1(91.395,68.301) 91.395,68.305 U1.V12@91.81,68.72
  Bottom Layer w0.127: v1(89.561,57.353) 89.561,58.369 89.177,58.752 89.177,58.849 86.982,61.045 86.982,65.333 88.497,66.849 90.622,66.849 91.007,67.233 91.007,67.68 90.985,67.702 90.985,67.891 v1(91.395,68.301)
TX_D5_N: U1.Y14 U5.D11 | length 13.7
  Top Layer w0.127: U5.D11@89.154,56.934 88.748,57.341 88.748,58.406 86.639,60.514 86.639,65.282 88.275,66.917 90.024,66.917 90.21,67.103 U1.Y14@90.21,67.12
TX_D5_P: U1.W14 U5.E12 | length 13.9
  Top Layer w0.127: U5.E12@89.954,57.734 89.605,58.084 89.605,58.325 89.299,58.63 88.882,58.63 86.893,60.619 86.893,65.176 88.38,66.663 90.238,66.663 90.653,67.078 90.967,67.078 U1.W14@91.01,67.12
TX_FRAME_N: RX10.2 U1.W16 U5.H9 | length 16.1
  Top Layer w0.127: v1@90.63,65.136 U1.W16@91.023,65.529 ; U5.H9@92.354,55.334 92.354,55.339 92.745,55.729 v1(92.745,55.734)
  Bottom Layer w0.127: RX10.2@89.941,64.382 89.966,64.382 90.63,65.046 v1(90.63,65.132) 90.597,65.165 90.597,65.432 90.523,65.507 90.092,65.507 89.432,64.846 89.432,61.568 91.135,59.864 92.844,59.864 92.94,59.768 93.559,59.149 93.559,57.826 93.142,57.408 93.142,56.131 92.747,55.737 92.745,55.737 v1(92.745,55.734)
TX_FRAME_P: U1.V16 U5.G9 | length 16.5
  Top Layer w0.127: v1@91.43,65.136 U1.V16@91.823,65.529 ; U5.G9@91.554,55.334 91.563,55.334 91.956,55.728 91.964,55.728 v1(91.964,55.718)
  Bottom Layer w0.127: v1(91.43,65.132) 91.366,65.132 90.737,65.761 89.987,65.761 89.178,64.951 89.178,61.463 91.03,59.61 92.739,59.61 92.761,59.588 93.305,59.044 93.305,57.961 92.344,57 92.344,56.106 91.964,55.726 v1(91.964,55.718)
TXNRX: U1.R14 U5.H4 | length 23.5
  Top Layer w0.127: U5.H4@92.354,51.334 v1(92.754,50.934) ; v1@93.817,66.727 U1.R14@94.21,67.12
  Bottom Layer w0.127: v1(92.754,50.934) 93.144,50.544 93.965,50.544 93.97,50.539 94.489,50.539 94.755,50.804 94.755,51.092 95.961,52.299 95.961,53.462 97.285,54.786 97.285,55.681 98.209,56.605 98.209,60.171 96.876,61.505 96.876,63.896 96.682,64.089 96.682,65.598 96.342,65.938 95.123,65.938 94.742,66.319 94.259,66.319 v1(93.853,66.726)
UART_RX: P2.11 U1.C12 | length 42.1
  Top Layer w0.127: U1.C12@103.81,68.72 103.821,68.72 104.181,69.081 v1(104.192,69.081)
  Top Layer w0.152: P2.11@118.745,90.424 120.117,89.052 120.117,81.813 122.123,79.807 v1(122.123,73.584)
  Bottom Layer w0.102: v1(104.192,69.081) 104.241,69.081 104.259,69.063 107.978,69.063 108.031,69.01 108.085,68.956 108.085,68.415 109.393,67.107 115.838,67.107 117.178,68.447 117.178,70.826 120.215,73.863 121.844,73.863 v1(122.123,73.584)
UART_TX: P2.12 U1.B12 | length 41.8
  Top Layer w0.102: U1.B12@104.61,68.72 104.657,68.673 104.928,68.673 105.3,68.301 105.689,68.301 106.823,67.167 109.161,67.167 110.284,66.044 114.281,66.044 116.588,68.351 119.151,68.351 119.355,68.555 v1@121.514,68.555
  Top Layer w0.152: P2.12@118.796,87.884 P2.12@118.745,87.884 119.736,86.893 119.736,81.763 121.818,79.68 121.818,73.928 121.666,73.776 121.666,73.381 122.276,72.771 122.968,72.771 123.596,72.143 123.596,70.714 121.514,68.631 v1@121.514,68.555
  other v1: 121.527,68.622
USB2_5V: C137.1 J2.1 P2.15 R64.2 R66.1 R67.1 | length 91.2
  Top Layer w0.254: v1@124.028,111.125 124.028,111.608 124.968,112.547 140.106,112.547 142.875,109.779 142.875,82.067 140.335,79.527 140.335,73.92 137.231,70.815 v1(137.211,70.815) 136.645,70.815 R66.1@136.62,70.79 ; R67.1@131.928,63.823 135.858,63.823 137.363,65.329 137.363,66.65 ; C137.1@136.62,68.25 136.645,68.224 137.338,68.224 v1(137.363,68.199) 137.363,66.65 ; R64.2@138.735,63.861 138.735,65.278 137.363,66.65 ; v1(142.076,68.467) J2.1@143.845,68.467
  Bottom Layer w0.254: P2.15@121.285,110.744 123.605,110.744 123.975,111.114 v1(124.028,111.114) ; v1(137.211,70.815) 138.43,70.815 140.778,68.467 v1(142.076,68.467) ; v1(137.363,68.199) 138.074,68.199 138.328,68.453 v1@142.091,68.453
USB_ID: J2.4 U4.23 | length 10
  Top Layer w0.152: U4.23@134.224,71.303 v1@137.141,71.303 ; v1(142.291,70.409) 143.837,70.409 J2.4@143.845,70.417
  Bottom Layer w0.152: v1(137.141,71.367) 138.309,71.367 139.267,70.409 v1(142.291,70.409)
USB_OTG_N: J2.2 P2.17 U4.19 | length 91.3
  Top Layer w0.102: P2.17@121.285,105.664 121.285,106.76 121.345,106.82 123.076,106.82 123.393,107.137 123.393,112.008 124.39,113.005 140.044,113.005 143.154,109.895 143.154,81.857 140.691,79.393 140.691,70.848 142.21,69.328 142.836,69.328 142.896,69.268 142.896,69.266 143.045,69.117 J2.2@143.845,69.117 144.645,69.117 144.794,69.266 144.794,69.268 144.854,69.328 144.997,69.328 145.491,68.834 145.491,67.437 143.967,65.913 138.782,65.913 138.024,66.672 138.024,68.5 137.356,69.168 134.682,69.168 134.547,69.303 U4.19@134.224,69.303
USB_OTG_P: J2.3 P2.16 U4.18 | length 92.1
  Top Layer w0.102: P2.16@121.285,108.204 121.285,107.108 121.345,107.048 122.981,107.048 123.165,107.232 123.165,112.103 124.295,113.233 140.139,113.233 143.383,109.989 143.383,81.763 140.919,79.299 140.919,70.942 142.305,69.556 142.836,69.556 142.896,69.616 142.896,69.618 143.045,69.767 J2.3@143.845,69.767 144.645,69.767 144.794,69.618 144.794,69.616 144.854,69.556 145.092,69.556 145.72,68.928 145.72,67.342 144.062,65.684 138.724,65.684 138.579,65.829 137.939,66.468 137.795,66.613 137.795,68.406 137.262,68.939 134.682,68.939 134.547,68.803 U4.18@134.224,68.803
USB_VBUS: R66.2 U4.22 | length 1.6
  Top Layer w0.102: U4.22@134.224,70.803 135.756,70.803 R66.2@135.77,70.79
USR_BTN: R19.2 U1.C5 USR_BTN.2 | length 26.3
  Top Layer w0.102: U1.C5@103.81,74.32 104.203,73.927 104.203,73.922 104.808,73.922 105.004,74.117 105.004,74.422 105.308,74.727 107.39,74.727 108.202,75.54 111.912,75.54 113.055,76.683 v1(113.132,76.683) ; v1(116.967,75.873) 116.978,75.884 121.234,75.884 v1(121.245,75.895) ; v1(123.555,77.41) 123.546,77.419 123.546,78.486 123.347,78.684 USR_BTN.2@123.747,78.684
  Bottom Layer w0.102: v1(113.132,76.683) 116.158,76.683 v1(116.967,75.873) ; v1(121.245,75.895) 122.707,75.895 123.717,76.904 R19.2@124.511,76.904 ; v1(123.555,77.41) 124.006,77.41 R19.2@124.511,76.904 ; R19.2@124.287,77.154 R19.2@124.536,76.904 R19.2@124.511,76.904
USR_LED: Q2.1 R65.1 U1.C8 | length 19.6
  Top Layer w0.102: v1(114.071,74.778) 114.097,74.752 114.628,74.752 115.149,74.231 117.284,74.231 Q2.1@119.151,72.365 120.53,72.365 R65.1@120.606,72.288
  Top Layer w0.127: U1.C8@103.81,71.92 104.203,72.314 v1(104.203,72.361)
  Bottom Layer w0.102: v1(104.203,72.361) 105.213,72.361 105.37,72.518 106.306,72.518 106.485,72.339 106.985,72.339 107.268,72.622 107.268,73.402 108.314,74.447 113.741,74.447 114.021,74.727 v1@114.046,74.727
VCC1P8: C143.2 C144.2 CP2.1 CP3.2 LP1.2 RP2.1 U5.H12 X4.4 | length 37.9
  Top Layer w0.127: U5.H12@92.354,57.734 92.354,57.796 92.583,58.025 92.583,58.42 92.786,58.623 v1(92.786,58.649) ; v1(99.254,56.058) 100.575,54.737 103.175,54.737 105.664,57.226 v1(106.756,57.226)
  Top Layer w0.305: C143.2@102.387,55.829 102.387,57.337 X4.4@102.683,57.633 104.254,57.633 104.623,58.002 C144.2@104.648,58.002
  Top Layer w0.5: v1(106.756,57.226) CP2.1@107.823,57.226 109.823,57.226 110.178,56.871 112.153,56.871 LP1.2@113.019,57.736 ; RP2.1@110.344,60.731 112.089,60.731 112.419,60.401 CP3.2@112.419,60.274 112.419,58.335 LP1.2@113.019,57.736 ; LP1.2@113.843,57.736 LP1.2@113.019,57.736
  Layer 2 w0.127: v1(92.786,58.649) 92.786,58.598 93.218,59.03 95.898,59.03 98.895,56.032 v1@99.263,56.032
  Bottom Layer w0.305: v1(103.911,57.658) 106.285,57.658 106.717,57.226 v1(106.756,57.226)
VCC_1V0: C2.2 C33.2 C34.2 C35.2 C36.2 C37.2 C38.2 C39.2 C49.2 C50.2 C51.2 C52.2 C53.2 C57.2 C67.2 L1.2 R7.1 R9.1 U1.G7 U1.G11 U1.G13 U1.H10 U1.H12 U1.J7 U1.J13 U1.K12 U1.L7 U1.L13 U1.M12 U1.N7 U1.N13 U1.P8 U1.P12 U1.R7 U1.R13 U6.14 | length 23.3
  Top Layer w0.25: U6.14@70.884,72.413 70.884,71.001 72.542,69.342 75.463,69.342 v1(76.048,69.926)
  Top Layer w0.305: v1(93.81,73.079) 93.839,73.079 94.198,72.72 U1.R7@94.21,72.72 ; v1@94.617,72.314 U1.P8@95.01,71.92 ; v1(95.41,73.105) 95.418,73.105 95.802,72.72 U1.N7@95.81,72.72
  Top Layer w0.356: v1(93.771,67.521) 93.796,67.521 94.196,67.92 U1.R13@94.21,67.92 ; v1@94.621,68.344 U1.P12@94.997,68.72 ; v1(95.417,67.521) 95.417,67.527 U1.N13@95.81,67.92 ; U1.M12@96.61,68.72 v1@97.003,69.114 ; v1(96.991,73.105) 97.016,73.105 97.401,72.72 U1.L7@97.41,72.72 ; v1(97.088,67.505) 97.088,67.531 97.41,67.852 U1.L13@97.41,67.92 ; U1.K12@98.21,68.72 v1@98.603,69.114 ; U1.J13@99.01,67.92 v1@99.403,67.527 ; U1.J7@99.01,72.72 v1@99.403,73.114 ; U1.H12@99.81,68.72 v1@100.203,69.114 ; U1.H10@99.81,70.32 v1@100.203,70.714 ; U1.G13@100.61,67.92 v1@101.003,67.527 ; U1.G11@100.61,69.52 v1@101.003,69.914 ; U1.G7@100.61,72.72 100.61,72.73 100.956,73.076 v1(100.99,73.076)
  Bottom Layer w0.107: v1(95.41,73.105) 95.424,73.105 95.424,73.091 95.828,72.687 96.976,72.687 C57.2@97.003,72.713
  Bottom Layer w0.356: v1(94.595,68.344) 94.613,68.362 95.217,68.362 C35.2@95.282,68.428 ; v1(97.003,69.139) 97.016,69.152 97.016,69.743 C34.2@97.028,69.755 ; v1(97.088,67.505) C39.2@97.79,67.506 ; C33.2@98.494,68.504 98.585,68.594 98.585,69.121 v1(98.603,69.139) ; C36.2@99.238,66.897 99.263,66.897 99.385,67.019 99.385,67.044 99.41,67.069 99.41,67.509 v1(99.429,67.527) ; v1@100.185,69.121 v1(100.203,69.139) 100.203,69.114 100.226,69.09 100.226,68.423 C38.2@100.349,68.301 C38.2@100.464,68.416
  other v1: 101.029,67.527 101.003,69.939 77.8,70.256 100.203,70.739 77.8,70.942 77.673,72.034 76.225,72.06 76.911,72.06 94.61,72.314 77.546,72.847 99.403,73.139 77.546,73.558 77.546,74.295 77.546,74.981 76.759,75.692 77.445,75.692 76.759,76.454 77.445,76.454 76.759,77.191 77.445,77.191 76.784,77.876 77.47,77.876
